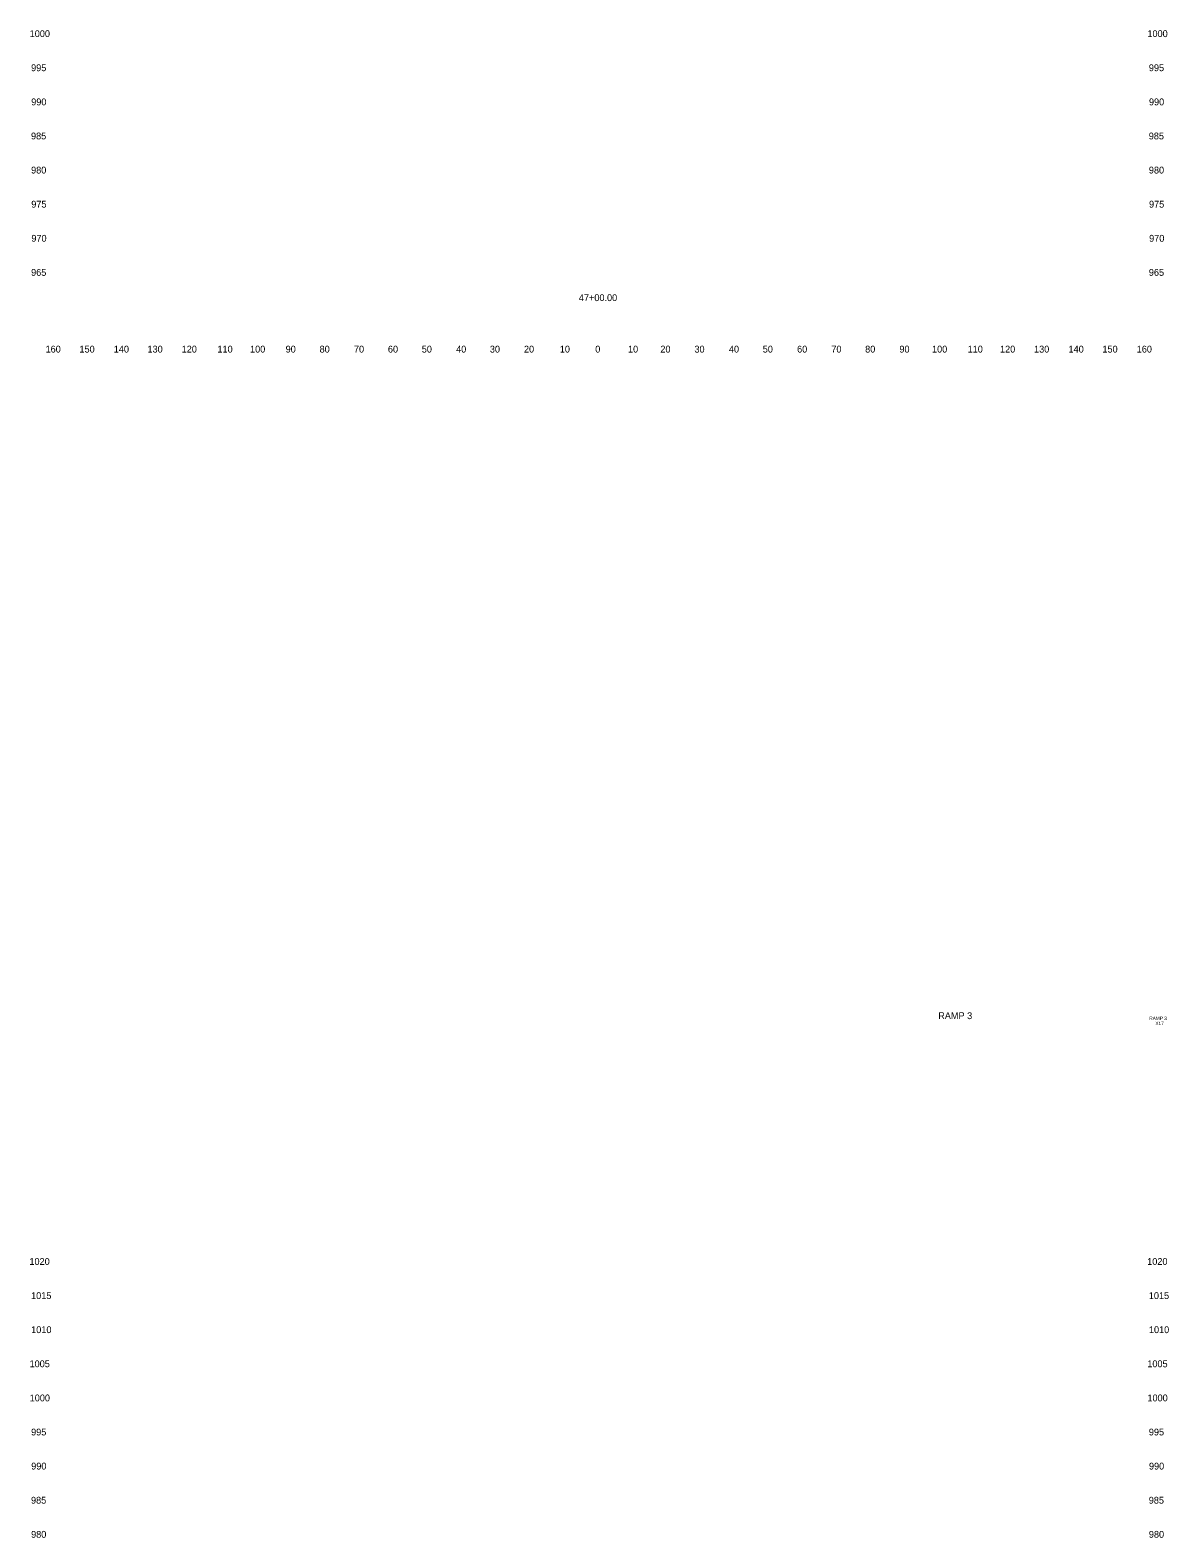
# Model space of a CAD drawing. Extents: x 4994 to 5843, y 4997 to 8804.
# Drawn here: x 5508.6 to 5842.5, y 7450 to 7892 of the extents above; entities that cross this region are included whole.
import ezdxf

# ---------------------------------------------------------------- set-up
doc = ezdxf.new("R2010")
doc.units = 0
for name, color, linetype in [('RD_SHT_ID', 7, 'Continuous'), ('RD_XS_TX_Offset', 7, 'Continuous'), ('RD_XS_TX_Station', 7, 'Continuous')]:
    doc.layers.add(name, color=color, linetype=linetype)

msp = doc.modelspace()

# ---------------------------------------------------------------- texts
at = {"layer": 'RD_SHT_ID'}
for s, height, p in [('RAMP 3', 2, (5774.89, 7602.06)), ('RAMP 3', 1, (5836.78, 7601.8)), ('X17', 1, (5838.57, 7600.3))]:
    msp.add_text(s, height=height, dxfattribs=at).set_placement(p)
at = {"layer": 'RD_XS_TX_Offset'}
for s, p in [('1000', (5508.44, 7890)), ('1000', (5836.24, 7890)), ('995', (5508.86, 7880)), ('995', (5836.66, 7880)), ('990', (5508.89, 7870)), ('990', (5836.69, 7870)), ('985', (5508.83, 7860)), ('985', (5836.63, 7860)), ('980', (5508.86, 7850)), ('980', (5836.66, 7850)), ('975', (5508.91, 7840)), ('975', (5836.71, 7840)), ('970', (5508.94, 7830)), ('970', (5836.74, 7830)), ('965', (5508.86, 7820)), ('965', (5836.66, 7820)), ('160', (5513.1, 7797.5)), ('150', (5523.04, 7797.5)), ('140', (5533.1, 7797.5)), ('130', (5542.99, 7797.5)), ('120', (5553.01, 7797.5)), ('110', (5563.51, 7797.5)), ('100', (5573.07, 7797.5)), ('90', (5583.5, 7797.5)), ('80', (5593.46, 7797.5)), ('70', (5603.54, 7797.5)), ('60', (5613.5, 7797.5)), ('50', (5623.43, 7797.5)), ('40', (5633.5, 7797.5)), ('30', (5643.39, 7797.5)), ('20', (5653.4, 7797.5)), ('10', (5663.91, 7797.5)), ('0', (5674.3, 7797.5)), ('0', (5674.3, 7797.5)), ('10', (5683.91, 7797.5)), ('20', (5693.4, 7797.5)), ('30', (5703.39, 7797.5)), ('40', (5713.5, 7797.5)), ('50', (5723.43, 7797.5)), ('60', (5733.5, 7797.5)), ('70', (5743.54, 7797.5)), ('80', (5753.46, 7797.5)), ('90', (5763.5, 7797.5)), ('100', (5773.07, 7797.5)), ('110', (5783.51, 7797.5)), ('120', (5793.01, 7797.5)), ('130', (5802.99, 7797.5)), ('140', (5813.1, 7797.5)), ('150', (5823.04, 7797.5)), ('160', (5833.1, 7797.5)), ('1020', (5508.37, 7530)), ('1020', (5836.17, 7530)), ('1015', (5508.85, 7520)), ('1015', (5836.65, 7520)), ('1010', (5508.88, 7510)), ('1010', (5836.68, 7510)), ('1005', (5508.4, 7500)), ('1005', (5836.2, 7500)), ('1000', (5508.44, 7490)), ('1000', (5836.24, 7490)), ('995', (5508.86, 7480)), ('995', (5836.66, 7480)), ('990', (5508.89, 7470)), ('990', (5836.69, 7470)), ('985', (5508.83, 7460)), ('985', (5836.63, 7460)), ('980', (5508.86, 7450)), ('980', (5836.66, 7450))]:
    msp.add_text(s, height=2, dxfattribs=at).set_placement(p)
at = {"layer": 'RD_XS_TX_Station'}
msp.add_text('47+00.00', height=2, dxfattribs=at).set_placement((5669.5, 7812.59))

doc.saveas('drawing.dxf')
